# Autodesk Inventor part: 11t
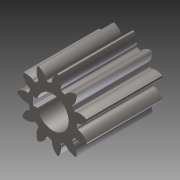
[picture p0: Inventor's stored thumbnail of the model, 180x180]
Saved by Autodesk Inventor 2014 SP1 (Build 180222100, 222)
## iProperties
Created: 2014-11
Part Number: 11t
Material: Steel
Document SubType Name: Modeling
Designer: Michael
Density: 7.85 g/cm^3
Appearance: Steel
Mass: 18.2383 g
Surface Area: 23.9266 cm^2
Volume: 2.32336 cm^3
Title: 217-3107-STEP.STEP
Description: STEP AP214
Creation Date: 2013-12-09
Sending System: SolidWorks 2013
Preprocessor: SwSTEP 2.0
Author: Michael
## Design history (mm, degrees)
node "11t1"
node "Split Line6"
node "Base1"
